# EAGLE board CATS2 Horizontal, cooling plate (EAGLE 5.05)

No outline drawn. Coordinates in mm, seen from the top.
Copper layers (1*16): Top 0.035mm / dielectric 1.5mm / Bottom 0.035mm
Design rules "default": minimum track width 10mil, minimum drill 0.6mm, track to track 8mil, track to pad 8mil, pad to pad 8mil, via to via 8mil, smd to smd 8mil, copper to edge 40mil, drill to drill 8mil, minimum pad ring 10mil, minimum via ring 8mil, stop-mask expansion 4mil, vias tented up to drill 0mil, thermal gap 10mil
Holes 3.5 mm at 275,98 244.5,98 260,44 419,142 388.5,142 404,196 49,44 124,44 199,44 323,98 292.5,98 308,44 371,142 340.5,142 356,196 371,98 340.5,98 356,44 323,142 292.5,142 308,196 419,98 388.5,98 404,44 275,142 244.5,142 260,196 312,-63
Holes 6 mm at 260,12 404,228 25,12 49,12 25,92 73,92 25,185 73,185 100,12 124,12 100,92 148,92 100,185 148,185 175,12 199,12 175,92 223,92 175,185 223,185 308,12 356,228 356,12 308,228 404,12 260,228 175,228 100,228 25,228 428,12 312,-57
Holes 3 mm at 260,64 404,176 49,64 124,64 199,64 308,64 356,176 356,64 308,176 404,64 260,176 312,-68
tKeepout: area 18,84.5 to 80,192.5; area 93,84.5 to 155,192.5; area 168,84.5 to 230,192.5; area 385,129 to 423,155; area 337,129 to 375,155; area 289,129 to 327,155; area 241,129 to 279,155; area 240.5,85 to 278.5,111; area 288.5,85 to 326.5,111; area 336.5,85 to 374.5,111; area 384.5,85 to 422.5,111

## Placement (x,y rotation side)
E$1  [TITLEBLOCK_PCB]  341,-50 0 top

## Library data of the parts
E$1 = QuantumOptics

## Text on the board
Document: 240 | 228 | 196 | 185 | 176 | 159 | 3/4" | 4 pl | 142 | 1/16-NPT | 4 pl | 120 | 98 | 92 | 64 | 64 | 44 | 44 | 12 | 0 | 1/2" ref | 0 | 25 | 49 | 73 | 100 | 124 | 148 | 175 | 199 | 223 | 244.5 | 260 | 275 | 292.5 | 308 | 323 | 340.5 | 356 | 371 | 388.5 | 404 | 419 | 428 | 440 | NOTES: | 1) Material: Aluminum, 6061, 1/2". | CATS2 Horizontal, | 2) Flatness under FETs is 50um/100mm, roughness Rz 10. | Tap M6x1 | 30 places | FET Cooling Plate | 3) Water channels milled to leave 3mm material. | Tap M4x0.7 | A. Stummer, Nov 2009 | 4) Water channel capped far side with aluminum plate and welded. | 27 places | A | Drill 3mm | 5) Water channel fittings: Swagelok B-400-1-1 or similar, 1/4 in. Tube OD x 1/16 in. Male NPT. | 11 places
